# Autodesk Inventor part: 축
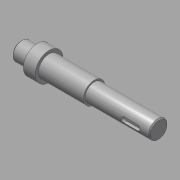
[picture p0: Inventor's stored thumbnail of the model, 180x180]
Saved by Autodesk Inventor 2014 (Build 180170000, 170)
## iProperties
Created: 2015-09
Part Number: 축
Material: 강철, 연강
Document SubType Name: Modeling
Designer: mduedu
Density: 7.86 g/cm^3
Appearance: 강철
Mass: 277.762 g
Surface Area: 88.1273 cm^2
Volume: 35.3387 cm^3
Author: mduedu
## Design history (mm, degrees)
sketch "스케치1"
  geometry: L1 (-64, 0)-(64, 0); L2 (-64, 0)-(-64, 8.5); L3 (-64, 8.5)-(-49, 8.5); L4 (-49, 8.5)-(-49, 13); L5 (-49, 13)-(-38, 13); L6 (-38, 13)-(-38, 10); L7 (-38, 10)-(4, 10); L8 (4, 10)-(4, 8.5); L9 (4, 8.5)-(64, 8.5); L10 (64, 8.5)-(64, 0); 2 further points
  constraints: 20 end point, 5 parallel, 2 horizontal, 2 perpendicular, 1 coincident, 1 midpoint, 1 vertical
  dimensions: "d0" = 128 distance of L1.start L1.end; "d2" = 11 distance of L4.end L5.end; "d3" = 42 distance of L6.end L7.end; "d4" = 60 distance of L8.end L9.end; "d5" = 17 diameter of L3 L1; "d6" = 17 diameter of L9 L1; "d7" = 20 diameter of L7 L1; "d8" = 26 diameter of L5 L1
revolve "회전1" sketch "스케치1" stored, may be unused: angle "d9" = 90 deg
node "작업 평면1"
sketch "스케치2"
  geometry: L1 (5.5, 2.5)-(18.5, 2.5); L2 (18.5, -2.5)-(5.5, -2.5); L3 (5.5, 2.5)-(18.5, -2.5); L4 (18.5, 2.5)-(5.5, -2.5); L5 (30, -8.5)-(30, 8.5) reference; A1 r 2.5 centre (5.5, 0) between (5.5, 2.5) and (5.5, -2.5); A2 r 2.5 centre (18.5, 0) between (18.5, -2.5) and (18.5, 2.5); 2 further points
  constraints: 8 end point, 4 point on circle, 4 tangent, 2 centre point, 2 midpoint, 1 horizontal, 1 horizontal alignment, 1 parallel
  dimensions: "d10" = 18 dimension on A2 A1; "d12" = 9 distance edge to line of A2 L5; "d13" = 5 distance between parallel lines of L2 L1
extrude "돌출1" cut sketch "스케치2" distance "d14" = 3; taper "d15" = 0 deg
node "작업 평면2"
sketch "스케치4"
  geometry: L1 (7, -3)-(-9, -3); L2 (-9, 3)-(7, 3); L3 (-21, 10)-(-21, -10) reference; A1 r 3 centre (-9, 0) between (-9, 3) and (-9, -3); A2 r 3 centre (7, 0) between (7, -3) and (7, 3); 1 further point
  constraints: 4 end point, 4 point on circle, 4 tangent, 2 centre point, 1 horizontal, 1 horizontal alignment, 1 parallel
  dimensions: "d16" = 22 dimension on A1 A2; "d18" = 6 distance between parallel lines of L2 L1; "d19" = 9 distance edge to line of A1 L3
extrude "돌출2" cut sketch "스케치4" distance "d20" = 3.5; taper "d21" = 0 deg
sketch "스케치5"
  geometry: L1 (4, 8.5)-(64, 8.5) reference; L2 (4, -8.5)-(64, -8.5) reference; L3 (37, 8.5)-(37, -8.5); L4 (37, -6.5)-(35, -8.5); L5 (37, -8.5)-(35, -8.5); L6 (37, -8.5)-(37, -6.5); L7 (4, -10)-(4, 10) reference; 1 further point
  constraints: 8 end point, 4 point on line, 1 collinear, 1 perpendicular
  dimensions: "d22" = 4 diameter of L4.end L3; "d24" = 45 deg angle of L3 L4; "d26" = 33 distance between parallel lines of L3 L7
revolve "회전2" sketch "스케치5" stored, may be unused: angle "d27" = 90 deg
chamfer "모따기1" distance "d28" = 1; stored, may be unused: second distance "d29" = 2, angle "d30" = 45 deg
node "솔리드1"
